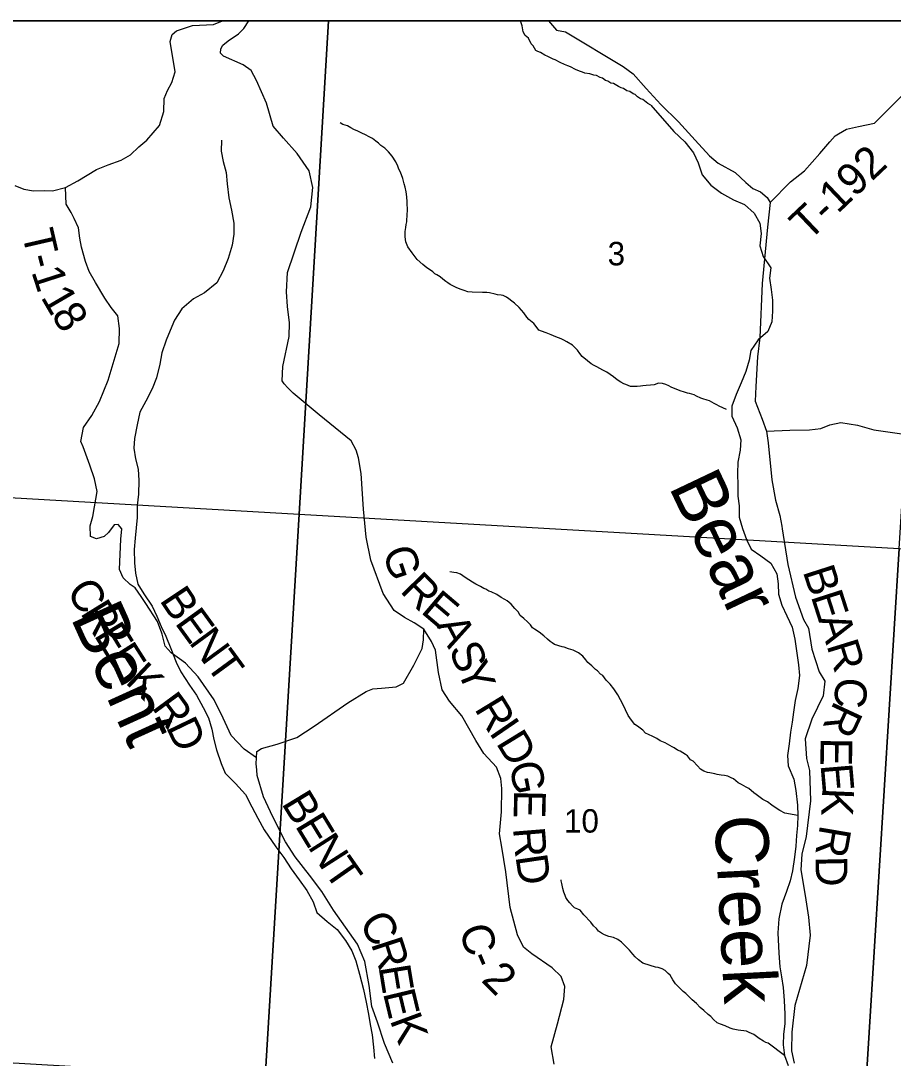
# Model space of a CAD drawing. Extents: x 0 to 34, y 0 to 22.
# Drawn here: x 5.409 to 6.969, y 19.045 to 20.9 of the extents above; entities that cross this region are included whole.
import ezdxf

# ---------------------------------------------------------------- set-up
doc = ezdxf.new("R2010")
doc.units = 0
for name, color, linetype in [('GM_X_County', 7, 'Continuous'), ('GM_X_County_Road', 7, 'Continuous'), ('GM_X_County_Road_Text', 7, 'Continuous'), ('GM_X_Minor_River', 7, 'Continuous'), ('GM_X_Minor_River_Text', 7, 'Continuous'), ('GM_X_Section', 7, 'Continuous'), ('GM_X_Section_Text', 7, 'Continuous'), ('GM_X_Township', 7, 'Continuous'), ('GM_X_Township_Road', 7, 'Continuous'), ('GM_X_Township_Road_Text', 7, 'Continuous'), ('GM_X_Township_ROW', 7, 'Continuous'), ('SH_Data', 7, 'Continuous')]:
    doc.layers.add(name, color=color, linetype=linetype)

msp = doc.modelspace()

# ---------------------------------------------------------------- linework, layer by layer
at = {"layer": 'GM_X_County'}
msp.add_lwpolyline([(9.4175, 16.6203), (9.4175, 20.9), (2.6175, 20.9), (2.6175, 15.1694)], dxfattribs=at)
at = {"layer": 'GM_X_County_Road'}
for points in [[(6.3629, 19.0347), (6.3571, 19.0654), (6.3684, 19.1064), (6.38, 19.15), (6.3819, 19.1736), (6.3754, 19.191), (6.359, 19.2069), (6.3226, 19.2319), (6.3078, 19.2436), (6.2971, 19.2656), (6.2841, 19.3145), (6.276, 19.3782), (6.2694, 19.4226), (6.2652, 19.4461), (6.2685, 19.4859), (6.2692, 19.5273), (6.2676, 19.5455), (6.2596, 19.5656), (6.2368, 19.5902), (6.2227, 19.6133), (6.1976, 19.6572), (6.1756, 19.6837), (6.1626, 19.7038), (6.1561, 19.7345), (6.1507, 19.7744), (6.1435, 19.7899), (6.1294, 19.8122), (6.1123, 19.8236), (6.0952, 19.833), (6.0763, 19.8455), (6.0572, 19.8758), (6.0347, 19.9353), (6.0267, 19.9766), (6.0216, 20.0267), (6.0173, 20.0904), (6.0131, 20.1185), (6.0089, 20.1325), (5.9997, 20.1488), (5.9427, 20.1957), (5.896, 20.2343), (5.8862, 20.2438), (5.8797, 20.2506), (5.8766, 20.2563), (5.8777, 20.2821), (5.8886, 20.3352), (5.8893, 20.3602), (5.8858, 20.3891), (5.8838, 20.4152), (5.886, 20.4502), (5.9105, 20.5219), (5.9278, 20.5671), (5.9312, 20.602), (5.9247, 20.6316), (5.9033, 20.6627), (5.8786, 20.6903), (5.86, 20.7115), (5.8485, 20.7524), (5.8306, 20.7934), (5.8211, 20.8112), (5.8067, 20.821), (5.7714, 20.8365), (5.7661, 20.8421), (5.7664, 20.8497), (5.7702, 20.8562), (5.7797, 20.8642), (5.7982, 20.8767), (5.8077, 20.8862), (5.8166, 20.9)], [(6.3526, 20.9), (6.3669, 20.8832), (6.3831, 20.8801), (6.486, 20.8185), (6.5042, 20.8048), (6.5274, 20.7791), (6.5536, 20.7503), (6.5848, 20.7193), (6.6148, 20.6867), (6.6403, 20.6587), (6.6562, 20.6451), (6.6862, 20.6285), (6.7056, 20.6111), (6.7181, 20.6001), (6.7318, 20.5941), (6.7436, 20.5838), (6.7489, 20.5751), (6.7441, 20.5307), (6.7344, 20.4302), (6.7305, 20.3338), (6.7264, 20.2993), (6.7231, 20.2461), (6.722, 20.22), (6.7346, 20.1877), (6.7426, 20.1661), (6.7453, 20.1453), (6.752, 20.0793), (6.7585, 20.0429), (6.7665, 20.0156), (6.77, 19.9966), (6.7707, 19.9918), (6.7707, 19.9918)], [(6.7707, 19.9918), (6.7807, 19.928), (6.7941, 19.8692), (6.8086, 19.8294), (6.8178, 19.8139), (6.8232, 19.7767), (6.8365, 19.7361), (6.8468, 19.7195), (6.8438, 19.6929), (6.8235, 19.6511), (6.8114, 19.6162), (6.8138, 19.5809), (6.8195, 19.5593), (6.8208, 19.5054), (6.8134, 19.4413), (6.8055, 19.4102), (6.804, 19.3821), (6.8117, 19.3358), (6.8175, 19.2971), (6.8202, 19.2653), (6.8139, 19.211), (6.7932, 19.1393), (6.7877, 19.0918), (6.787, 19.0584), (6.7916, 19.0362)], [(5.831, 19.5605), (5.8309, 19.5606), (5.8301, 19.5713), (5.8306, 19.582), (5.8312, 19.5933), (5.8392, 19.599), (5.8676, 19.6067), (5.9024, 19.6186), (5.9338, 19.6391), (5.9936, 19.6803), (6.0266, 19.7008), (6.0387, 19.7058), (6.0538, 19.707), (6.08, 19.7093), (6.0932, 19.7154), (6.1117, 19.7481), (6.1268, 19.7777), (6.1291, 19.7929), (6.1294, 19.8122)], [(6.074, 19.0362), (6.0595, 19.0715), (6.0469, 19.1098), (6.0366, 19.1378), (6.0316, 19.175), (6.0239, 19.2178), (6.011, 19.2489), (5.968, 19.3099), (5.947, 19.3432), (5.9254, 19.3724), (5.8995, 19.4053), (5.882, 19.4322), (5.8595, 19.4766), (5.8432, 19.5126), (5.8317, 19.5508), (5.831, 19.5605)]]:
    msp.add_lwpolyline(points, dxfattribs=at)
at = {"layer": 'GM_X_Minor_River'}
for points in [[(6.5357, 20.7492), (6.5304, 20.7523), (6.5211, 20.7593), (6.5169, 20.7605), (6.512, 20.764), (6.5076, 20.7682), (6.5038, 20.7694), (6.4978, 20.7733), (6.4929, 20.7749), (6.4866, 20.7788), (6.4824, 20.7801), (6.4779, 20.7824), (6.4689, 20.7879), (6.464, 20.7887), (6.4584, 20.7922), (6.4546, 20.7934), (6.449, 20.7973), (6.4452, 20.7985), (6.4385, 20.8021), (6.4336, 20.8029), (6.4264, 20.8049), (6.4177, 20.8062), (6.4136, 20.8082), (6.4083, 20.8098), (6.4008, 20.813), (6.3922, 20.8177), (6.3873, 20.8193), (6.3809, 20.822), (6.3734, 20.8256), (6.3647, 20.8299), (6.361, 20.8315), (6.3516, 20.8362), (6.3463, 20.8382), (6.3381, 20.8433), (6.3336, 20.8449), (6.3298, 20.8468), (6.3254, 20.8552), (6.3213, 20.8587), (6.3169, 20.8687), (6.3106, 20.8737), (6.3073, 20.8802), (6.3056, 20.8909), (6.3038, 20.8962), (6.3028, 20.9)], [(6.5357, 20.7492), (6.5766, 20.7019), (6.5962, 20.6836), (6.6121, 20.6639), (6.6204, 20.6457), (6.6272, 20.6244), (6.643, 20.6062), (6.6619, 20.5918), (6.6831, 20.5797), (6.7028, 20.5713), (6.7202, 20.5561), (6.7307, 20.5379), (6.733, 20.5197), (6.7307, 20.4977), (6.7367, 20.4787), (6.7503, 20.4582), (6.748, 20.44), (6.751, 20.4195), (6.7532, 20.4006), (6.7532, 20.3809), (6.7517, 20.3619), (6.7448, 20.3444), (6.7274, 20.3293), (6.7145, 20.3103), (6.7114, 20.2929), (6.7053, 20.2732), (6.697, 20.2527), (6.6879, 20.2315), (6.6803, 20.211), (6.6802, 20.1928), (6.69, 20.1723), (6.6968, 20.151), (6.6953, 20.1321), (6.6914, 20.1108), (6.6907, 20.0904), (6.6914, 20.0691), (6.6913, 20.0501), (6.6936, 20.0327), (6.6936, 20.0122), (6.6996, 19.9925), (6.7064, 19.9728), (6.7147, 19.9553), (6.7321, 19.9432), (6.7502, 19.9303), (6.7608, 19.9113), (6.763, 19.8931), (6.7637, 19.8749), (6.7698, 19.8551), (6.7788, 19.8362), (6.7886, 19.8157), (6.7931, 19.7944), (6.7961, 19.7732), (6.7999, 19.7482), (6.8013, 19.7292), (6.7983, 19.7064), (6.7937, 19.6844), (6.7906, 19.664), (6.7883, 19.6458), (6.7853, 19.6283), (6.783, 19.6071), (6.7799, 19.5866), (6.7814, 19.5676), (6.7912, 19.5441), (6.795, 19.5236), (6.7979, 19.4978), (6.7987, 19.4789), (6.7979, 19.4614), (6.7963, 19.4432), (6.7948, 19.4242), (6.7925, 19.4045), (6.7887, 19.3802), (6.7849, 19.362), (6.778, 19.3431), (6.7696, 19.3203), (6.7643, 19.2945), (6.7628, 19.2695), (6.7642, 19.2331), (6.7664, 19.2088), (6.7694, 19.1906), (6.7724, 19.1716), (6.7739, 19.1481), (6.7754, 19.1238), (6.7754, 19.1064), (6.7731, 19.0882), (6.7723, 19.0692), (6.7745, 19.0502), (6.7813, 19.032)], [(6.1, 20.5765), (6.099, 20.5853), (6.0981, 20.594), (6.0963, 20.6024), (6.0945, 20.6085), (6.092, 20.618), (6.0881, 20.6295), (6.0851, 20.6349), (6.0833, 20.6402), (6.0797, 20.6479), (6.0731, 20.6579), (6.0664, 20.6656), (6.0597, 20.6721), (6.0526, 20.6772), (6.0488, 20.6814), (6.044, 20.6849), (6.038, 20.6892), (6.032, 20.6923), (6.0252, 20.6959), (6.0185, 20.699), (6.0117, 20.7026), (6.0046, 20.7057), (5.9989, 20.7085), (5.9929, 20.712), (5.9847, 20.7148), (5.9798, 20.7175)], [(5.768, 20.6864), (5.7672, 20.6666), (5.771, 20.6484), (5.7763, 20.6287), (5.7777, 20.6082), (5.7807, 20.5832), (5.786, 20.5612), (5.7897, 20.5384), (5.7897, 20.5187), (5.7867, 20.499), (5.7798, 20.4747), (5.7707, 20.4527), (5.7593, 20.4315), (5.7373, 20.4133), (5.7176, 20.4027), (5.6971, 20.3852), (5.6835, 20.3647), (5.6759, 20.3465), (5.669, 20.3291), (5.6614, 20.3063), (5.6576, 20.2859), (5.6515, 20.2616), (5.6439, 20.2419), (5.6325, 20.2199), (5.6219, 20.2001), (5.6173, 20.1774), (5.612, 20.1531), (5.6112, 20.1357), (5.6142, 20.1167), (5.6187, 20.0985), (5.6202, 20.078), (5.6194, 20.0537), (5.6171, 20.0332), (5.617, 20.012), (5.6132, 19.9748), (5.6116, 19.9544), (5.6124, 19.9308), (5.6138, 19.9126), (5.6184, 19.8929), (5.6289, 19.8755), (5.644, 19.8534), (5.6523, 19.8352), (5.6599, 19.817), (5.6682, 19.7996), (5.6772, 19.7776), (5.687, 19.7533), (5.6953, 19.7358), (5.7104, 19.7123), (5.7233, 19.6941), (5.7353, 19.6721), (5.7444, 19.6539), (5.7504, 19.6334), (5.7542, 19.6152), (5.7587, 19.5962), (5.767, 19.572), (5.7745, 19.5545), (5.7927, 19.5363), (5.8108, 19.5166), (5.8221, 19.4945), (5.8327, 19.4741), (5.844, 19.4536), (5.8652, 19.4232), (5.8795, 19.4042), (5.8923, 19.3838), (5.9067, 19.364), (5.9203, 19.3451), (5.9316, 19.3246), (5.9384, 19.3056), (5.9565, 19.2897), (5.9747, 19.2752), (5.9898, 19.2555), (6.0011, 19.2373), (6.0079, 19.2191), (6.0147, 19.1956), (6.0215, 19.1682), (6.0267, 19.1455), (6.0305, 19.1242), (6.0335, 19.1053), (6.0372, 19.0871), (6.0395, 19.0651), (6.0417, 19.0446)], [(6.6707, 20.205), (6.658, 20.2109), (6.6538, 20.2133), (6.6486, 20.2156), (6.6403, 20.2203), (6.6362, 20.2215), (6.6287, 20.2243), (6.6249, 20.2255), (6.6174, 20.2291), (6.6132, 20.231), (6.6049, 20.2335), (6.6012, 20.2343), (6.5955, 20.2359), (6.588, 20.2383), (6.5718, 20.2447), (6.5677, 20.247), (6.5624, 20.2497), (6.5564, 20.2514), (6.5492, 20.2519), (6.5416, 20.2493), (6.5348, 20.2483), (6.5272, 20.2477), (6.5211, 20.247), (6.5173, 20.2467), (6.5112, 20.2461), (6.5055, 20.2458), (6.4995, 20.2463), (6.4908, 20.2494), (6.4871, 20.2506), (6.4822, 20.2538), (6.4755, 20.2581), (6.4691, 20.2631), (6.4627, 20.2674), (6.4568, 20.272), (6.45, 20.2752), (6.4444, 20.2783), (6.4391, 20.2811), (6.4342, 20.2834), (6.429, 20.2869), (6.4223, 20.292), (6.4129, 20.2997), (6.4089, 20.3051), (6.4044, 20.3113), (6.4003, 20.3155), (6.3955, 20.3202), (6.3854, 20.326), (6.3797, 20.3292), (6.3752, 20.3311), (6.3655, 20.3351), (6.3576, 20.3387), (6.3485, 20.3422), (6.3399, 20.345), (6.3354, 20.347), (6.3324, 20.3508), (6.3261, 20.3586), (6.3175, 20.3659), (6.3138, 20.3701), (6.3083, 20.3778), (6.3001, 20.3875), (6.2919, 20.3952), (6.287, 20.3987), (6.2818, 20.403), (6.2777, 20.4061), (6.2717, 20.4085), (6.2679, 20.4093), (6.2611, 20.4101), (6.2573, 20.4114), (6.2471, 20.4134), (6.2426, 20.4139), (6.2343, 20.4144), (6.2161, 20.4147), (6.2082, 20.4156), (6.2018, 20.4176), (6.1946, 20.4204), (6.1875, 20.4232), (6.1818, 20.4259), (6.177, 20.4283), (6.1725, 20.4314), (6.1687, 20.4337), (6.1635, 20.438), (6.1586, 20.4423), (6.153, 20.4458), (6.1493, 20.4473), (6.1455, 20.4512), (6.1396, 20.4551), (6.1351, 20.4582), (6.128, 20.464), (6.1179, 20.4733), (6.1086, 20.4849), (6.1009, 20.496), (6.0972, 20.5048), (6.0963, 20.5139), (6.0964, 20.5234), (6.0977, 20.5306), (6.0982, 20.5359), (6.099, 20.5405), (6.0991, 20.5458), (6.0996, 20.5496), (6.1, 20.5549), (6.1005, 20.5598), (6.1, 20.5765)], [(6.7987, 19.4789), (6.7754, 19.4833), (6.7664, 19.488), (6.7582, 19.4934), (6.7518, 19.4977), (6.7439, 19.5036), (6.7357, 19.5079), (6.7237, 19.5164), (6.7196, 19.5199), (6.711, 19.5273), (6.7058, 19.53), (6.6975, 19.5347), (6.6915, 19.5375), (6.6833, 19.5445), (6.6792, 19.5464), (6.6732, 19.5492), (6.6675, 19.5504), (6.6615, 19.5513), (6.6543, 19.5522), (6.6501, 19.5534), (6.6411, 19.5554), (6.6369, 19.5562), (6.6301, 19.5586), (6.6245, 19.5622), (6.6189, 19.5679), (6.6111, 19.5764), (6.6066, 19.5788), (6.6011, 19.5857), (6.5973, 19.5884), (6.588, 19.5939), (6.5835, 19.5959), (6.5775, 19.6002), (6.5737, 19.6021), (6.5655, 19.6068), (6.5613, 19.6088), (6.5523, 19.6124), (6.5463, 19.617), (6.5392, 19.6206), (6.5313, 19.6237), (6.526, 19.6265), (6.5212, 19.6315), (6.5115, 19.6389), (6.507, 19.642), (6.5011, 19.6493), (6.4952, 19.6578), (6.49, 19.6681), (6.4864, 19.6758), (6.4816, 19.6861), (6.4765, 19.6949), (6.4695, 19.7057), (6.4628, 19.7141), (6.4554, 19.7211), (6.4495, 19.7292), (6.4457, 19.7319), (6.4401, 19.7377), (6.4364, 19.7404), (6.4301, 19.7466), (6.423, 19.7524), (6.4196, 19.7574), (6.4137, 19.7639), (6.4062, 19.7698), (6.3965, 19.7745), (6.3882, 19.7769), (6.3807, 19.7801), (6.3769, 19.7809), (6.3633, 19.7849), (6.3592, 19.7876), (6.3555, 19.7904), (6.3506, 19.7942), (6.3443, 19.8004), (6.3357, 19.8066), (6.3278, 19.8125), (6.3237, 19.8148), (6.3204, 19.8198), (6.3152, 19.8252), (6.3085, 19.8314), (6.3021, 19.8368), (6.2981, 19.843), (6.2921, 19.8492), (6.2858, 19.8569), (6.2787, 19.8627), (6.2746, 19.8654), (6.2678, 19.8689), (6.2603, 19.874), (6.2498, 19.8787), (6.2461, 19.8799), (6.2408, 19.8838), (6.2371, 19.885), (6.2307, 19.8885), (6.2228, 19.8925), (6.2168, 19.896), (6.2101, 19.9007), (6.2037, 19.9049), (6.1955, 19.9104), (6.1887, 19.9128), (6.1834, 19.9133), (6.1762, 19.9145)], [(6.774, 19.0507), (6.7745, 19.0502), (6.7454, 19.0718), (6.7413, 19.0734), (6.7371, 19.0757), (6.7293, 19.0804), (6.7199, 19.0878), (6.7117, 19.0913), (6.7064, 19.0933), (6.692, 19.0951), (6.6826, 19.0968), (6.6773, 19.0987), (6.6683, 19.1031), (6.66, 19.1059), (6.6544, 19.1086), (6.6477, 19.1141), (6.6428, 19.1195), (6.638, 19.1233), (6.6305, 19.1303), (6.6238, 19.1361), (6.6175, 19.1427), (6.6097, 19.1493), (6.5981, 19.1608), (6.5933, 19.1647), (6.5858, 19.1721), (6.5799, 19.1782), (6.5751, 19.1852), (6.5703, 19.1936), (6.5666, 19.1967), (6.561, 19.2021), (6.5561, 19.2048), (6.5486, 19.2072), (6.544, 19.2081), (6.5346, 19.2109), (6.5214, 19.2153), (6.5136, 19.2211), (6.5076, 19.2262), (6.5035, 19.2312), (6.4976, 19.2381), (6.4905, 19.2454), (6.4831, 19.2524), (6.4763, 19.2571), (6.4688, 19.261), (6.4602, 19.263), (6.4526, 19.2658), (6.4474, 19.2686), (6.4418, 19.2725), (6.4384, 19.2771), (6.4332, 19.2817), (6.428, 19.2886), (6.4158, 19.3014), (6.4091, 19.3099), (6.4049, 19.3114), (6.3993, 19.3138), (6.3956, 19.3173), (6.3908, 19.3227), (6.387, 19.3269), (6.3833, 19.3323), (6.3823, 19.3361), (6.3797, 19.3419), (6.3783, 19.3487), (6.3766, 19.3575), (6.3755, 19.3624), (6.375, 19.3642)]]:
    msp.add_lwpolyline(points, dxfattribs=at)
at = {"layer": 'GM_X_Section'}
for p, q in [((5.9593, 20.9), (4.8782, 20.9)), ((7.0384, 20.9), (5.9593, 20.9))]:
    msp.add_line(p, q, dxfattribs=at)
for points in [[(4.8782, 20.9), (4.8284, 20.0797), (5.9068, 20.018), (5.9593, 20.9)], [(5.9593, 20.9), (5.9068, 20.018), (6.9795, 19.9566), (7.0384, 20.9)]]:
    msp.add_lwpolyline(points, dxfattribs=at)
for points in [[(4.8284, 20.0797), (5.9068, 20.018), (5.8458, 19.0101), (4.7704, 19.0729)], [(5.9068, 20.018), (6.9795, 19.9566), (6.9173, 18.9472), (5.8458, 19.0101)], [(6.9795, 19.9566), (8.0453, 19.8934), (7.9764, 18.8836), (6.9173, 18.9472)]]:
    msp.add_lwpolyline(points, close=True, dxfattribs=at)
at = {"layer": 'GM_X_Township'}
msp.add_line((8.2133, 20.9), (2.7154, 20.9), dxfattribs=at)
at = {"layer": 'GM_X_Township_Road'}
for points in [[(5.3985, 20.6052), (5.4145, 20.5988), (5.4315, 20.5962), (5.4512, 20.5966), (5.4656, 20.5959), (5.4891, 20.602), (5.5107, 20.6138), (5.5444, 20.634), (5.5652, 20.6424), (5.5887, 20.6508), (5.605, 20.66), (5.6198, 20.6748), (5.6345, 20.6866), (5.6572, 20.7125), (5.6647, 20.7375), (5.6654, 20.7607), (5.6711, 20.7751), (5.679, 20.7895), (5.685, 20.8085), (5.6762, 20.8628), (5.6799, 20.8753), (5.6871, 20.8821), (5.7, 20.886), (5.7159, 20.8917), (5.7538, 20.8934), (5.7696, 20.9)], [(6.8559, 20.6836), (6.865, 20.6941), (6.8709, 20.6976), (6.8854, 20.7059), (6.9068, 20.7107)], [(6.7489, 20.5751), (6.7852, 20.612), (6.8105, 20.6318), (6.8377, 20.6626), (6.8559, 20.6836)], [(5.5385, 20.017), (5.5454, 20.0581), (5.5408, 20.0809), (5.5324, 20.1055), (5.5202, 20.1385), (5.5164, 20.1476), (5.5212, 20.1726), (5.536, 20.1943), (5.5499, 20.2194), (5.5654, 20.2577), (5.585, 20.323), (5.5856, 20.35), (5.5826, 20.3727), (5.5704, 20.3875), (5.5594, 20.4042), (5.5426, 20.4322), (5.5312, 20.4515), (5.5247, 20.4693), (5.5174, 20.4951), (5.5144, 20.511), (5.5124, 20.53), (5.5041, 20.5467), (5.4991, 20.5569), (5.4903, 20.572), (5.4891, 20.602)], [(6.7426, 20.1661), (6.7843, 20.1678), (6.8192, 20.1686), (6.8397, 20.1709), (6.8556, 20.1778), (6.8753, 20.182), (6.9052, 20.1771), (6.9344, 20.1689), (6.9636, 20.1644), (6.997, 20.1599)], [(5.6617, 19.8033), (5.6613, 19.805), (5.6536, 19.8262), (5.6323, 19.858), (5.6243, 19.8709), (5.6133, 19.886), (5.6046, 19.8921), (5.592, 19.9042), (5.5855, 19.919), (5.5881, 19.9732), (5.5895, 19.9915), (5.5831, 19.9994), (5.5759, 19.999), (5.5657, 19.9849), (5.5581, 19.9781), (5.5445, 19.9735), (5.5338, 19.978), (5.5327, 19.997), (5.5379, 20.0137), (5.5384, 20.0167), (5.5385, 20.017)], [(5.8306, 19.582), (5.8085, 19.5975), (5.7853, 19.6221), (5.7708, 19.6531), (5.7548, 19.6857), (5.7259, 19.727), (5.7035, 19.7512), (5.678, 19.7701), (5.667, 19.7819), (5.6617, 19.8031), (5.6617, 19.8033)]]:
    msp.add_lwpolyline(points, dxfattribs=at)
at = {"layer": 'GM_X_Township_ROW'}
msp.add_lwpolyline([(6.9068, 20.7107), (6.9354, 20.7171), (7.0741, 20.8548), (7.1195, 20.9)], dxfattribs=at)
at = {"layer": 'SH_Data'}
msp.add_line((2.6, 20.9), (9.4, 20.9), dxfattribs=at)

# ---------------------------------------------------------------- texts
at = {"layer": 'GM_X_County_Road_Text'}
for s, rotation, p in [('G', 288.4972, (6.055, 19.951)), ('B', 287.8015, (6.8069, 19.9158)), ('R', 314.5601, (6.0855, 19.8797)), ('E', 319.6673, (6.1223, 19.8427)), ('E', 287.8, (6.8212, 19.8713)), ('A', 287.7994, (6.8342, 19.8309)), ('A', 297.6945, (6.1511, 19.8197)), ('R', 287.1918, (6.8494, 19.7834)), ('S', 291.9785, (6.1737, 19.7768)), ('Y', 292.0918, (6.1881, 19.7411)), ('C', 266.0901, (6.8666, 19.7273)), ('R', 301.3844, (6.219, 19.67)), ('R', 245.0349, (6.8648, 19.686)), ('I', 304.4134, (6.245, 19.6274)), ('D', 301.4569, (6.2578, 19.6088)), ('E', 269.1162, (6.8393, 19.6185)), ('G', 281.0291, (6.282, 19.5711)), ('E', 274.8739, (6.8389, 19.5698)), ('B', 301.2654, (5.8741, 19.5009)), ('E', 268.7099, (6.2913, 19.5252)), ('K', 267.5659, (6.8424, 19.5293)), ('E', 301.3006, (5.8983, 19.4609)), ('N', 302.5893, (5.9211, 19.4235)), ('R', 274.7108, (6.2891, 19.4564)), ('R', 260.4126, (6.8385, 19.4638)), ('T', 305.0084, (5.9495, 19.3792)), ('D', 278.3397, (6.2934, 19.406)), ('D', 271.2006, (6.8299, 19.4062)), ('C', 300.0719, (6.0125, 19.2878)), ('C', 286.474, (6.1923, 19.2763)), ('R', 287.9695, (6.0346, 19.2503)), ('-', 293.3904, (6.2081, 19.2245)), ('E', 279.3151, (6.0485, 19.2082)), ('2', 315.1761, (6.2306, 19.1837)), ('E', 283.4991, (6.0563, 19.1618)), ('K', 290.1929, (6.0683, 19.1135))]:
    msp.add_text(s, height=0.0568, rotation=rotation, dxfattribs=at).set_placement(p)
at = {"layer": 'GM_X_Minor_River_Text'}
for s, height, rotation, p in [('Bear', 0.09467, 295.4319, (6.5668, 20.0673)), ('Bent', 0.09466, 294.3903, (5.4971, 19.8333)), ('Creek', 0.09467, 272.9759, (6.6494, 19.4781))]:
    msp.add_text(s, height=height, rotation=rotation, dxfattribs=at).set_placement(p)
at = {"layer": 'GM_X_Section_Text'}
for s, height, p in [('3', 0.0419, (6.4583, 20.4627)), ('10', 0.04186, (6.3804, 19.4485))]:
    msp.add_text(s, height=height, rotation=0, dxfattribs=at).set_placement(p)
at = {"layer": 'GM_X_Township_Road_Text'}
for s, height, rotation, p in [('T-192', 0.05682, 43.5661, (6.8176, 20.5043)), ('T', 0.0568, 283.0025, (5.4105, 20.5206)), ('-', 0.0568, 284.8191, (5.4205, 20.4773)), ('1', 0.0568, 287.8547, (5.4274, 20.4516)), ('1', 0.0568, 300.2802, (5.4436, 20.406)), ('8', 0.0568, 301.7358, (5.4621, 20.3745)), ('C', 0.0568, 303.1751, (5.4889, 19.88)), ('B', 0.0568, 303.7326, (5.6558, 19.8641)), ('R', 0.0568, 301.7231, (5.5142, 19.8413)), ('E', 0.0568, 306.0039, (5.6831, 19.8233)), ('E', 0.0568, 301.4873, (5.5387, 19.8016)), ('N', 0.0568, 306.2065, (5.7082, 19.7887)), ('E', 0.0568, 302.4233, (5.5614, 19.7645)), ('T', 0.0568, 306.2048, (5.7378, 19.7484)), ('K', 0.0568, 316.6775, (5.594, 19.7168)), ('R', 0.0568, 306.3646, (5.6417, 19.6723)), ('D', 0.0568, 295.8256, (5.6679, 19.6371))]:
    msp.add_text(s, height=height, rotation=rotation, dxfattribs=at).set_placement(p)

doc.saveas('drawing.dxf')
